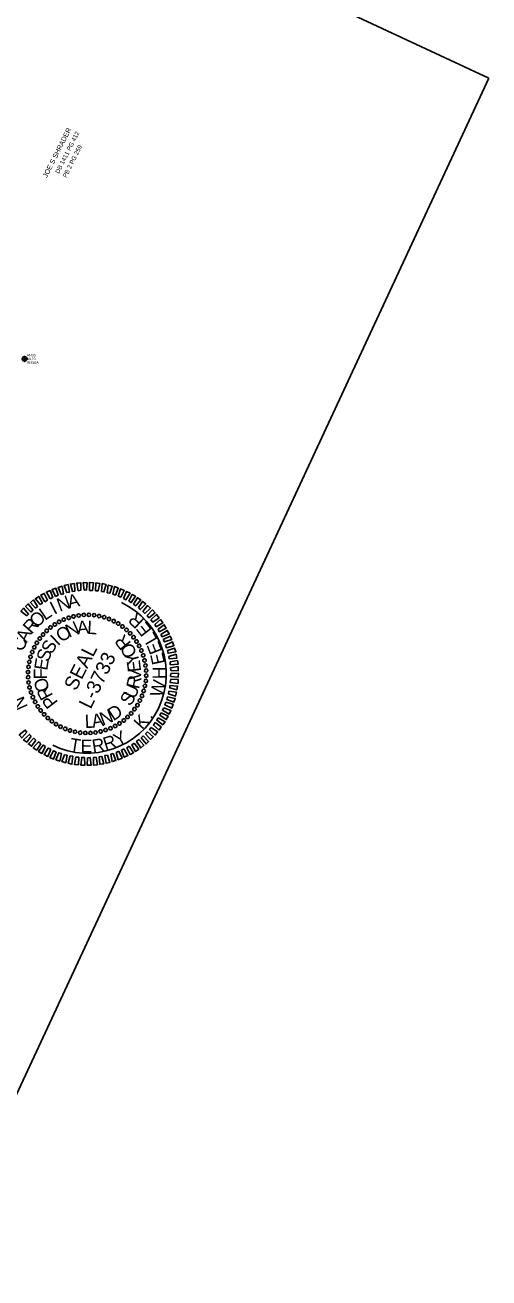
# Model space of a CAD drawing. Extents: x 2532037 to 2533565, y 713396 to 716867.
# Drawn here: x 2533093 to 2533565, y 714704 to 715980 of the extents above; entities that cross this region are included whole.
import ezdxf

# ---------------------------------------------------------------- set-up
doc = ezdxf.new("R2010")
doc.units = 0
for name, color, linetype in [('Exist Environmental Wetland Boundary Cogo Comment', 7, 'Continuous'), ('Exist Environmental Wetland Boundary Cogo Elevation', 7, 'Continuous'), ('Exist Environmental Wetland Boundary Cogo Number', 7, 'Continuous'), ('Exist Environmental Wetland Boundary Cogo Point CELL', 7, 'Continuous'), ('Exist Property Deed Book Text', 7, 'Continuous'), ('Exist Property Owner Text', 7, 'Continuous'), ('Scratch_Level_0', 7, 'Continuous'), ('Sheet PDF Layout', 7, 'Continuous'), ('Sheet Professional Seal CELL', 7, 'Continuous')]:
    doc.layers.add(name, color=color, linetype=linetype)

msp = doc.modelspace()

# ---------------------------------------------------------------- linework, layer by layer
at = {"layer": 'Exist Environmental Wetland Boundary Cogo Point CELL'}
msp.add_lwpolyline([(2533092.2, 715643.1), (2533092.2, 715637.1), (2533092.2, 715640.1), (2533095.2, 715640.1), (2533089.2, 715640.1)], dxfattribs=at)
msp.add_circle((2533092.2, 715640.1), 2.34, dxfattribs=at)
at = {"layer": 'Scratch_Level_0'}
msp.add_arc((2533155.9, 715319.3), 80.7, 244.2438, 64.2438, dxfattribs=at)
at = {"layer": 'Sheet PDF Layout'}
for p, q in [((2532767.4, 716297.1), (2533565.2, 715925.9)), ((2533565.2, 715925.9), (2532997, 714704.4))]:
    msp.add_line(p, q, dxfattribs=at)
at = {"layer": 'Sheet Professional Seal CELL'}
for p, q in [((2533122.8, 715369.8), (2533122.8, 715369.8)), ((2533127.4, 715372.4), (2533127.4, 715372.4)), ((2533132.1, 715374.7), (2533132.1, 715374.7)), ((2533137, 715376.5), (2533137, 715376.5)), ((2533142.1, 715378.1), (2533142.1, 715378.1)), ((2533147.2, 715378.9), (2533147.2, 715378.9)), ((2533152.5, 715379.4), (2533152.5, 715379.4)), ((2533157.8, 715379.6), (2533157.8, 715379.6)), ((2533162.9, 715379.2), (2533162.9, 715379.2)), ((2533168.1, 715378.3), (2533168.1, 715378.3)), ((2533173.3, 715376.9), (2533173.3, 715376.9)), ((2533178.2, 715375.3), (2533178.2, 715375.3)), ((2533183, 715373.1), (2533183, 715373.1)), ((2533187.6, 715370.5), (2533187.6, 715370.5)), ((2533110.9, 715359.4), (2533110.9, 715359.4)), ((2533114.6, 715363.2), (2533114.6, 715363.2)), ((2533118.6, 715366.6), (2533118.6, 715366.6)), ((2533191.9, 715367.5), (2533191.9, 715367.5)), ((2533196, 715364.3), (2533196, 715364.3)), ((2533199.8, 715360.6), (2533199.8, 715360.6)), ((2533102.1, 715346.5), (2533102.1, 715346.5)), ((2533104.7, 715351.1), (2533104.7, 715351.1)), ((2533107.7, 715355.4), (2533107.7, 715355.4)), ((2533203.2, 715356.6), (2533203.2, 715356.6)), ((2533206.4, 715352.4), (2533206.4, 715352.4)), ((2533209, 715347.8), (2533209, 715347.8)), ((2533096.9, 715331.5), (2533096.9, 715331.5)), ((2533098.3, 715336.7), (2533098.3, 715336.7)), ((2533099.9, 715341.7), (2533099.9, 715341.7)), ((2533211.3, 715343.1), (2533211.3, 715343.1)), ((2533213.1, 715338.2), (2533213.1, 715338.2)), ((2533214.6, 715333.1), (2533214.6, 715333.1)), ((2533095.7, 715321.2), (2533095.7, 715321.2)), ((2533096, 715326.4), (2533096, 715326.4)), ((2533155.9, 715319.3), (2533155.9, 715319.3)), ((2533215.5, 715328), (2533215.5, 715328)), ((2533216, 715322.7), (2533216, 715322.7)), ((2533095.8, 715315.9), (2533095.8, 715315.9)), ((2533096.3, 715310.6), (2533096.3, 715310.6)), ((2533214.9, 715307.1), (2533214.9, 715307.1)), ((2533215.8, 715312.3), (2533215.8, 715312.3)), ((2533216.1, 715317.4), (2533216.1, 715317.4)), ((2533097.2, 715305.6), (2533097.2, 715305.6)), ((2533098.7, 715300.4), (2533098.7, 715300.4)), ((2533100.5, 715295.6), (2533100.5, 715295.6)), ((2533211.9, 715297), (2533211.9, 715297)), ((2533213.5, 715301.9), (2533213.5, 715301.9)), ((2533102.8, 715290.8), (2533102.8, 715290.8)), ((2533105.4, 715286.2), (2533105.4, 715286.2)), ((2533108.6, 715282), (2533108.6, 715282)), ((2533204.1, 715283.3), (2533204.1, 715283.3)), ((2533207.1, 715287.6), (2533207.1, 715287.6)), ((2533209.7, 715292.2), (2533209.7, 715292.2)), ((2533112, 715278), (2533112, 715278)), ((2533115.8, 715274.3), (2533115.8, 715274.3)), ((2533119.9, 715271.2), (2533119.9, 715271.2)), ((2533124.1, 715268.2), (2533124.1, 715268.2)), ((2533189, 715268.9), (2533189, 715268.9)), ((2533193.2, 715272), (2533193.2, 715272)), ((2533197.2, 715275.4), (2533197.2, 715275.4)), ((2533200.9, 715279.2), (2533200.9, 715279.2)), ((2533128.7, 715265.5), (2533128.7, 715265.5)), ((2533133.6, 715263.3), (2533133.6, 715263.3)), ((2533138.5, 715261.8), (2533138.5, 715261.8)), ((2533143.7, 715260.3), (2533143.7, 715260.3)), ((2533148.9, 715259.4), (2533148.9, 715259.4)), ((2533154, 715259.1), (2533154, 715259.1)), ((2533159.3, 715259.2), (2533159.3, 715259.2)), ((2533164.6, 715259.7), (2533164.6, 715259.7)), ((2533169.7, 715260.6), (2533169.7, 715260.6)), ((2533174.8, 715262.1), (2533174.8, 715262.1)), ((2533179.7, 715263.9), (2533179.7, 715263.9)), ((2533184.4, 715266.3), (2533184.4, 715266.3))]:
    msp.add_line(p, q, dxfattribs=at)
for points in [[(2533129.4, 715400.2), (2533126.5, 715407.3), (2533130.4, 715408.6), (2533131.9, 715401)], [(2533135.1, 715402.1), (2533132.6, 715409.4), (2533136.6, 715410.3), (2533138, 715402.6)], [(2533140.9, 715403.3), (2533138.9, 715410.8), (2533143, 715411.3), (2533143.5, 715403.6)], [(2533146.7, 715404), (2533145.3, 715411.7), (2533149.5, 715412.2), (2533149.5, 715404.5)], [(2533152.8, 715404.5), (2533151.9, 715412.4), (2533155.9, 715412.2), (2533155.4, 715404.8)], [(2533158.5, 715404.4), (2533158.3, 715412.4), (2533162.4, 715412.1), (2533161.4, 715404.4)], [(2533164.5, 715403.9), (2533164.8, 715411.9), (2533168.8, 715411.4), (2533167.3, 715403.9)], [(2533170.5, 715403.1), (2533171.3, 715411.3), (2533175.2, 715410.2), (2533173.1, 715402.8)], [(2533176.3, 715401.9), (2533177.5, 715409.7), (2533181.5, 715408.6), (2533178.9, 715401.5)], [(2533182, 715400.4), (2533183.8, 715408.2), (2533187.7, 715406.7), (2533184.8, 715399.6)], [(2533108, 715390), (2533103.3, 715395.9), (2533106.7, 715398.2), (2533110.3, 715391.4)], [(2533113, 715392.8), (2533108.6, 715399.6), (2533112.2, 715401.3), (2533115.4, 715394.5)], [(2533118.4, 715395.6), (2533114.4, 715402.5), (2533118.1, 715404.2), (2533120.9, 715397)], [(2533123.7, 715398.1), (2533120.2, 715405.3), (2533124.1, 715406.6), (2533126.3, 715399.4)], [(2533187.5, 715398.6), (2533190, 715406), (2533193.8, 715404.4), (2533190.2, 715397.5)], [(2533192.9, 715396.1), (2533196, 715403.2), (2533199.7, 715401.5), (2533195.5, 715394.8)], [(2533198.3, 715393.3), (2533201.9, 715400.3), (2533205.3, 715398.3), (2533200.8, 715391.9)], [(2533203.2, 715390.3), (2533207.2, 715396.9), (2533210.7, 715394.7), (2533205.5, 715388.5)], [(2533094.5, 715378.4), (2533088.5, 715383.3), (2533091.2, 715386.1), (2533096.3, 715380.3)], [(2533098.8, 715382.3), (2533093.2, 715388.1), (2533095.9, 715390.5), (2533100.7, 715384.4)], [(2533103.2, 715386.2), (2533098.1, 715392), (2533101.2, 715394.6), (2533105.5, 715388)], [(2533208.3, 715386.8), (2533212.4, 715393.1), (2533215.7, 715390.5), (2533210.1, 715384.8)], [(2533212.8, 715382.9), (2533217.4, 715388.9), (2533220.6, 715386.4), (2533214.7, 715380.9)], [(2533217.2, 715378.7), (2533222.4, 715384.5), (2533225.1, 715381.5), (2533218.9, 715376.5)], [(2533220.9, 715374.3), (2533226.6, 715379.8), (2533229.2, 715376.5), (2533222.8, 715372.1)], [(2533224.9, 715369.7), (2533230.5, 715374.6), (2533233.1, 715371.3), (2533226.3, 715367.4)], [(2533228.2, 715364.9), (2533234.4, 715369.4), (2533236.4, 715365.8), (2533229.4, 715362.2)], [(2533231, 715359.6), (2533237.5, 715363.6), (2533239.6, 715360.1), (2533232.4, 715357.2)], [(2533233.5, 715354.3), (2533240.5, 715357.9), (2533242.1, 715354.2), (2533234.8, 715351.9)], [(2533235.8, 715348.6), (2533242.9, 715351.9), (2533244.1, 715348), (2533236.7, 715346)], [(2533237.9, 715343.2), (2533244.9, 715345.6), (2533246.3, 715341.8), (2533238.4, 715340.4)], [(2533239.2, 715337.2), (2533246.6, 715339.4), (2533247.4, 715335.4), (2533239.6, 715334.5)], [(2533240.4, 715331.6), (2533247.9, 715332.9), (2533248.6, 715329.1), (2533240.6, 715328.6)], [(2533240.8, 715325.5), (2533248.6, 715326.7), (2533248.7, 715322.5), (2533241.1, 715322.8)], [(2533241.2, 715319.6), (2533248.9, 715320.1), (2533248.8, 715316.1), (2533241, 715316.8)], [(2533240.3, 715307.6), (2533248, 715307), (2533247.4, 715303.2), (2533240, 715305)], [(2533241.2, 715313.8), (2533248.8, 715313.5), (2533248.5, 715309.7), (2533240.5, 715310.7)], [(2533237.9, 715296), (2533245.7, 715294.4), (2533244.3, 715290.7), (2533237, 715293.3)], [(2533239.2, 715301.8), (2533247.1, 715300.7), (2533246.1, 715296.7), (2533238.7, 715299.2)], [(2533234, 715284.8), (2533241.3, 715282), (2533239.4, 715278.5), (2533232.6, 715282.3)], [(2533236.1, 715290.5), (2533243.5, 715288.4), (2533242.2, 715284.5), (2533235.1, 715287.8)], [(2533225.1, 715269.7), (2533231.5, 715265.4), (2533229.3, 715262.1), (2533223.5, 715267.2)], [(2533228.4, 715274.5), (2533235.3, 715270.6), (2533232.9, 715267.4), (2533226.8, 715272.1)], [(2533231.4, 715279.7), (2533238.4, 715276.3), (2533236.6, 715272.8), (2533230, 715277.2)], [(2533094.6, 715259.9), (2533089.4, 715254.1), (2533086.7, 715257.2), (2533092.9, 715262.2)], [(2533099, 715255.8), (2533094.4, 715249.8), (2533091.2, 715252.2), (2533097.1, 715257.7)], [(2533213, 715256.3), (2533218.6, 715250.5), (2533215.9, 715248.1), (2533211.1, 715254.2)], [(2533217.3, 715260.2), (2533223.2, 715255.4), (2533220.5, 715252.6), (2533215.5, 715258.3)], [(2533221.2, 715264.7), (2533227.7, 715260.3), (2533225.1, 715257), (2533219.6, 715262.7)], [(2533103.5, 715251.9), (2533099.4, 715245.6), (2533096.1, 715248.1), (2533101.6, 715253.8)], [(2533108.6, 715248.3), (2533104.6, 715241.7), (2533101.1, 715243.9), (2533106.3, 715250.1)], [(2533113.5, 715245.3), (2533109.9, 715238.4), (2533106.5, 715240.3), (2533111, 715246.8)], [(2533118.9, 715242.6), (2533115.8, 715235.4), (2533112.1, 715237.2), (2533116.3, 715243.8)], [(2533193.4, 715243), (2533197.4, 715236.1), (2533193.7, 715234.5), (2533190.9, 715241.7)], [(2533198.8, 715245.9), (2533203.2, 715239.1), (2533199.6, 715237.3), (2533196.4, 715244.1)], [(2533203.7, 715248.7), (2533208.5, 715242.8), (2533205.1, 715240.4), (2533201.5, 715247.2)], [(2533208.6, 715252.4), (2533213.7, 715246.7), (2533210.6, 715244), (2533206.3, 715250.6)], [(2533124.3, 715240.1), (2533121.8, 715232.6), (2533118, 715234.2), (2533121.6, 715241.1)], [(2533129.8, 715238.2), (2533128, 715230.5), (2533124.1, 715231.9), (2533127, 715239)], [(2533135.5, 715236.7), (2533134.3, 715228.9), (2533130.3, 715230), (2533132.9, 715237.1)], [(2533141.3, 715235.5), (2533140.4, 715227.4), (2533136.6, 715228.4), (2533138.7, 715235.8)], [(2533147.3, 715234.7), (2533147, 715226.8), (2533143, 715227.2), (2533144.5, 715234.7)], [(2533153.3, 715234.2), (2533153.5, 715226.3), (2533149.4, 715226.5), (2533150.4, 715234.3)], [(2533159, 715234.1), (2533159.9, 715226.3), (2533155.9, 715226.5), (2533156.4, 715233.8)], [(2533165.1, 715234.6), (2533166.5, 715226.9), (2533162.3, 715226.5), (2533162.3, 715234.2)], [(2533170.9, 715235.3), (2533172.9, 715227.8), (2533168.8, 715227.3), (2533168.3, 715235)], [(2533176.7, 715236.5), (2533179.2, 715229.2), (2533175.2, 715228.4), (2533173.8, 715236.1)], [(2533182.4, 715238.4), (2533185.3, 715231.3), (2533181.4, 715230), (2533179.9, 715237.6)], [(2533188.1, 715240.5), (2533191.6, 715233.4), (2533187.7, 715232), (2533185.5, 715239.2)]]:
    msp.add_lwpolyline(points, close=True, dxfattribs=at)
for centre, major_axis in [((2533122.9, 715369.7), (-0.95, 1.45)), ((2533127.4, 715372.3), (-0.82, 1.52)), ((2533132.1, 715374.6), (-0.68, 1.59)), ((2533137.1, 715376.5), (-0.54, 1.64)), ((2533142.1, 715377.9), (-0.4, 1.68)), ((2533147.3, 715378.9), (-0.25, 1.71)), ((2533152.5, 715379.4), (-0.1, 1.73)), ((2533157.7, 715379.5), (0.05, 1.73)), ((2533163, 715379.1), (0.2, 1.72)), ((2533168.2, 715378.2), (0.35, 1.69)), ((2533173.3, 715377), (0.5, 1.65)), ((2533178.2, 715375.2), (0.64, 1.6)), ((2533183, 715373.1), (0.78, 1.54)), ((2533187.6, 715370.5), (0.91, 1.47)), ((2533107.7, 715355.3), (-1.38, 1.03)), ((2533111, 715359.4), (-1.29, 1.15)), ((2533114.7, 715363.2), (-1.18, 1.26)), ((2533118.6, 715366.6), (-1.07, 1.36)), ((2533191.9, 715367.5), (1.03, 1.38)), ((2533196, 715364.2), (1.15, 1.29)), ((2533199.7, 715360.6), (1.26, 1.18)), ((2533203.2, 715356.6), (1.36, 1.07)), ((2533102.1, 715346.4), (-1.54, 0.78)), ((2533104.7, 715351), (-1.47, 0.91)), ((2533206.2, 715352.3), (1.45, 0.95)), ((2533208.9, 715347.8), (1.52, 0.82)), ((2533211.2, 715343.1), (1.59, 0.68)), ((2533097, 715331.6), (-1.69, 0.35)), ((2533098.3, 715336.7), (-1.65, 0.5)), ((2533100, 715341.6), (-1.6, 0.64)), ((2533213.1, 715338.2), (1.64, 0.54)), ((2533214.5, 715333.1), (1.68, 0.4)), ((2533095.7, 715321.2), (-1.73, 0.05)), ((2533096.1, 715326.4), (-1.72, 0.2)), ((2533215.5, 715327.9), (1.71, 0.25)), ((2533216, 715322.7), (1.73, 0.1)), ((2533216.1, 715317.5), (1.73, -0.05)), ((2533095.8, 715315.9), (-1.73, -0.1)), ((2533096.3, 715310.7), (-1.71, -0.25)), ((2533097.3, 715305.5), (-1.68, -0.4)), ((2533214.8, 715307.1), (1.69, -0.35)), ((2533215.7, 715312.2), (1.72, -0.2)), ((2533098.7, 715300.5), (-1.64, -0.54)), ((2533100.6, 715295.6), (-1.59, -0.68)), ((2533209.6, 715292.2), (1.54, -0.78)), ((2533211.8, 715297), (1.6, -0.64)), ((2533213.5, 715302), (1.65, -0.5)), ((2533102.9, 715290.8), (-1.52, -0.82)), ((2533105.6, 715286.3), (-1.45, -0.95)), ((2533108.6, 715282.1), (-1.36, -1.07)), ((2533200.8, 715279.2), (1.29, -1.15)), ((2533204.1, 715283.3), (1.38, -1.03)), ((2533207.1, 715287.6), (1.47, -0.91)), ((2533112.1, 715278.1), (-1.26, -1.18)), ((2533115.8, 715274.4), (-1.15, -1.29)), ((2533119.9, 715271.1), (-1.03, -1.38)), ((2533124.2, 715268.1), (-0.91, -1.47)), ((2533184.4, 715266.3), (0.82, -1.52)), ((2533188.9, 715269), (0.95, -1.45)), ((2533193.2, 715272), (1.07, -1.36)), ((2533197.1, 715275.5), (1.18, -1.26)), ((2533128.8, 715265.6), (-0.78, -1.54)), ((2533133.6, 715263.4), (-0.64, -1.6)), ((2533138.5, 715261.7), (-0.5, -1.65)), ((2533143.6, 715260.4), (-0.35, -1.69)), ((2533148.8, 715259.5), (-0.2, -1.72)), ((2533154.1, 715259.2), (-0.05, -1.73)), ((2533159.3, 715259.2), (0.1, -1.73)), ((2533164.5, 715259.7), (0.25, -1.71)), ((2533169.7, 715260.7), (0.4, -1.68)), ((2533174.7, 715262.2), (0.54, -1.64)), ((2533179.7, 715264), (0.68, -1.59))]:
    msp.add_ellipse(centre, major_axis=major_axis, ratio=0.999708, dxfattribs=at)

# ---------------------------------------------------------------- texts
at = {"layer": 'Exist Environmental Wetland Boundary Cogo Comment'}
msp.add_text('WB26A', height=2.5, dxfattribs=at).set_placement((2533094.7, 715635.1))
at = {"layer": 'Exist Environmental Wetland Boundary Cogo Elevation'}
msp.add_text('18.73', height=2.5, dxfattribs=at).set_placement((2533094.7, 715638.8))
at = {"layer": 'Exist Environmental Wetland Boundary Cogo Number'}
msp.add_text('RR39', height=2.5, dxfattribs=at).set_placement((2533094.7, 715642.6))
at = {"layer": 'Exist Property Deed Book Text'}
for s, p in [('DB 1411 PG 412', (2533127.2, 715828.2)), ('PB 2 PG 259', (2533134.8, 715824))]:
    msp.add_text(s, height=4.5, rotation=63.3607, dxfattribs=at).set_placement(p)
at = {"layer": 'Exist Property Owner Text'}
msp.add_text('JOE S SHRADER', height=5, rotation=63.3607, dxfattribs=at).set_placement((2533115, 715824))
at = {"layer": 'Sheet Professional Seal CELL'}
for s, height, rotation, p in [('N', 13.5, 20.0627, (2533128, 715382.5)), ('A', 13.5, 12.8609, (2533137.5, 715385.8)), ('O', 13.5, 41.6649, (2533104.4, 715365.6)), ('L', 13.5, 34.4646, (2533113, 715373.2)), ('I', 13.5, 27.2639, (2533122.4, 715379.4)), ('R', 13.5, 48.8649, (2533099.3, 715359.1)), ('N', 13.5, 24.7204, (2533137.6, 715356)), ('A', 13.5, 6.004, (2533146.2, 715359.4)), ('L', 13.5, 356.6446, (2533155.7, 715360.1)), ('R', 13.2, 137.1577, (2533214.8, 715373.9)), ('E', 13.2, 128.2134, (2533222.6, 715364.1)), ('A', 13.5, 63.2641, (2533094.5, 715350.3)), ('I', 13.5, 43.4334, (2533126.2, 715347.2)), ('O', 13.5, 34.0773, (2533129.8, 715350.8)), ('R', 13.5, 128.7131, (2533201.4, 715350.6)), ('L', 13.2, 120.042, (2533228.2, 715354.2)), ('C', 13.5, 70.4636, (2533091, 715341.4)), ('S', 13.5, 71.4994, (2533116.6, 715330.8)), ('S', 13.5, 62.1442, (2533120.2, 715338.7)), ('SEAL', 14.4, 63.2438, (2533144.5, 715301.2)), ('O', 13.5, 115.7039, (2533207.2, 715339.6)), ('E', 13.2, 111.0977, (2533232.8, 715342.5)), ('E', 13.5, 80.8548, (2533115.2, 715322.3)), ('L-3733', 14.4, 64.2438, (2533159.6, 715282.8)), ('Y', 13.5, 105.9104, (2533209.9, 715330.6)), ('E', 13.5, 96.8254, (2533211, 715321.9)), ('E', 13.2, 102.1534, (2533235.4, 715330.3)), ('F', 13.5, 90.2108, (2533115.1, 715313.8)), ('V', 13.5, 86.7322, (2533210.6, 715312.2)), ('H', 13.2, 90.5473, (2533236, 715314)), ('O', 13.5, 108.925, (2533118.1, 715303.6)), ('R', 13.5, 118.2834, (2533121.5, 715297.3)), ('U', 13.5, 65.7417, (2533204.4, 715293)), ('R', 13.5, 77.3202, (2533208.7, 715303.3)), ('W', 13.2, 76.58, (2533232.4, 715294.9)), ('N', 13.5, 113.6673, (2533095.8, 715285.8)), ('P', 13.5, 127.6427, (2533126.8, 715290.5)), ('S', 13.5, 56.466, (2533199.6, 715285.6)), ('N', 13.5, 20.8586, (2533171.7, 715266.5)), ('D', 13.5, 33.1319, (2533182.6, 715271)), ('L', 13.5, 1.8983, (2533153.7, 715264.2)), ('A', 13.5, 10.2475, (2533161.7, 715264.4)), ('K', 13.2, 48.6452, (2533212, 715261.9)), ('.', 13.2, 58.6771, (2533221.2, 715272.5)), ('R', 13.2, 17.8626, (2533174.7, 715241.3)), ('Y', 13.2, 27.1503, (2533187.1, 715245.3)), ('T', 13.2, 350.9726, (2533137.4, 715241.2)), ('E', 13.2, 359.6306, (2533149.3, 715239.3)), ('R', 13.2, 8.5749, (2533161.9, 715239.2))]:
    msp.add_text(s, height=height, rotation=rotation, dxfattribs=at).set_placement(p)

doc.saveas('drawing.dxf')
